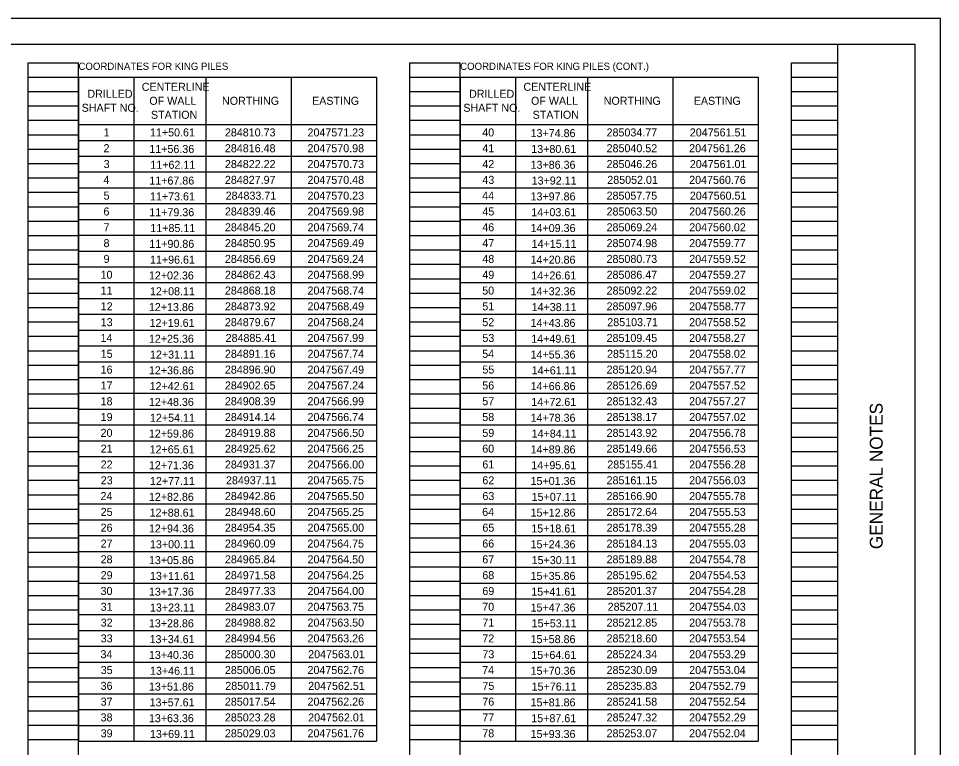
# Model space of a CAD drawing. Extents: x -15.5 to 34, y 0 to 22.
# Drawn here: x 16.07 to 34, y 7.82 to 22 of the extents above; entities that cross this region are included whole.
import ezdxf

# ---------------------------------------------------------------- set-up
doc = ezdxf.new("R2010")
doc.units = 0
for name, color, linetype in [('SH_Border', 7, 'Continuous'), ('SH_Cut_Line', 7, 'Continuous'), ('SH_Data', 7, 'Continuous'), ('SH_Text', 7, 'Continuous')]:
    doc.layers.add(name, color=color, linetype=linetype)

msp = doc.modelspace()

# ---------------------------------------------------------------- linework, layer by layer
at = {"layer": 'SH_Border'}
msp.add_line((32, 0.5), (32, 21.5), dxfattribs=at)
msp.add_lwpolyline([(1.5, 21.5), (33.5, 21.5), (33.5, 0.5), (1.5, 0.5)], close=True, dxfattribs=at)
at = {"layer": 'SH_Cut_Line'}
msp.add_lwpolyline([(0, 0), (34, 0), (34, 22), (0, 22)], close=True, dxfattribs=at)
at = {"layer": 'SH_Data'}
for p, q in [((16.26, 0.98), (16.26, 21.14)), ((16.26, 21.14), (17.24, 21.14)), ((17.24, 0.98), (17.24, 21.14)), ((23.68, 0.98), (23.68, 21.14)), ((23.68, 21.14), (24.66, 21.14)), ((24.66, 0.98), (24.66, 21.14)), ((31.1, 0.98), (31.1, 21.14)), ((31.1, 21.14), (32, 21.14)), ((32, 0.98), (32, 21.14)), ((16.26, 20.86), (17.24, 20.86)), ((23.68, 20.86), (24.66, 20.86)), ((31.1, 20.86), (32, 20.86)), ((16.26, 20.58), (17.24, 20.58)), ((23.68, 20.58), (24.66, 20.58)), ((31.1, 20.58), (32, 20.58)), ((16.26, 20.3), (17.24, 20.3)), ((23.68, 20.3), (24.66, 20.3)), ((31.1, 20.3), (32, 20.3)), ((16.26, 20.02), (17.24, 20.02)), ((23.68, 20.02), (24.66, 20.02)), ((31.1, 20.02), (32, 20.02)), ((16.26, 19.74), (17.24, 19.74)), ((23.68, 19.74), (24.66, 19.74)), ((31.1, 19.74), (32, 19.74)), ((16.26, 19.46), (17.24, 19.46)), ((23.68, 19.46), (24.66, 19.46)), ((31.1, 19.46), (32, 19.46)), ((16.26, 19.18), (17.24, 19.18)), ((23.68, 19.18), (24.66, 19.18)), ((31.1, 19.18), (32, 19.18)), ((16.26, 18.9), (17.24, 18.9)), ((23.68, 18.9), (24.66, 18.9)), ((31.1, 18.9), (32, 18.9)), ((16.26, 18.62), (17.24, 18.62)), ((23.68, 18.62), (24.66, 18.62)), ((31.1, 18.62), (32, 18.62)), ((16.26, 18.34), (17.24, 18.34)), ((23.68, 18.34), (24.66, 18.34)), ((31.1, 18.34), (32, 18.34)), ((16.26, 18.06), (17.24, 18.06)), ((23.68, 18.06), (24.66, 18.06)), ((31.1, 18.06), (32, 18.06)), ((16.26, 17.78), (17.24, 17.78)), ((23.68, 17.78), (24.66, 17.78)), ((31.1, 17.78), (32, 17.78)), ((16.26, 17.5), (17.24, 17.5)), ((23.68, 17.5), (24.66, 17.5)), ((31.1, 17.5), (32, 17.5)), ((16.26, 17.22), (17.24, 17.22)), ((23.68, 17.22), (24.66, 17.22)), ((31.1, 17.22), (32, 17.22)), ((16.26, 16.94), (17.24, 16.94)), ((23.68, 16.94), (24.66, 16.94)), ((31.1, 16.94), (32, 16.94)), ((16.26, 16.66), (17.24, 16.66)), ((23.68, 16.66), (24.66, 16.66)), ((31.1, 16.66), (32, 16.66)), ((16.26, 16.38), (17.24, 16.38)), ((23.68, 16.38), (24.66, 16.38)), ((31.1, 16.38), (32, 16.38)), ((16.26, 16.1), (17.24, 16.1)), ((23.68, 16.1), (24.66, 16.1)), ((31.1, 16.1), (32, 16.1)), ((16.26, 15.82), (17.24, 15.82)), ((23.68, 15.82), (24.66, 15.82)), ((31.1, 15.82), (32, 15.82)), ((16.26, 15.54), (17.24, 15.54)), ((23.68, 15.54), (24.66, 15.54)), ((31.1, 15.54), (32, 15.54)), ((16.26, 15.26), (17.24, 15.26)), ((23.68, 15.26), (24.66, 15.26)), ((31.1, 15.26), (32, 15.26)), ((16.26, 14.98), (17.24, 14.98)), ((23.68, 14.98), (24.66, 14.98)), ((31.1, 14.98), (32, 14.98)), ((16.26, 14.7), (17.24, 14.7)), ((23.68, 14.7), (24.66, 14.7)), ((31.1, 14.7), (32, 14.7)), ((16.26, 14.42), (17.24, 14.42)), ((23.68, 14.42), (24.66, 14.42)), ((31.1, 14.42), (32, 14.42)), ((16.26, 14.14), (17.24, 14.14)), ((23.68, 14.14), (24.66, 14.14)), ((31.1, 14.14), (32, 14.14)), ((16.26, 13.86), (17.24, 13.86)), ((23.68, 13.86), (24.66, 13.86)), ((31.1, 13.86), (32, 13.86)), ((16.26, 13.58), (17.24, 13.58)), ((23.68, 13.58), (24.66, 13.58)), ((31.1, 13.58), (32, 13.58)), ((16.26, 13.3), (17.24, 13.3)), ((23.68, 13.3), (24.66, 13.3)), ((31.1, 13.3), (32, 13.3)), ((16.26, 13.02), (17.24, 13.02)), ((23.68, 13.02), (24.66, 13.02)), ((31.1, 13.02), (32, 13.02)), ((16.26, 12.74), (17.24, 12.74)), ((23.68, 12.74), (24.66, 12.74)), ((31.1, 12.74), (32, 12.74)), ((16.26, 12.46), (17.24, 12.46)), ((23.68, 12.46), (24.66, 12.46)), ((31.1, 12.46), (32, 12.46)), ((16.26, 12.18), (17.24, 12.18)), ((23.68, 12.18), (24.66, 12.18)), ((31.1, 12.18), (32, 12.18)), ((16.26, 11.9), (17.24, 11.9)), ((23.68, 11.9), (24.66, 11.9)), ((31.1, 11.9), (32, 11.9)), ((16.26, 11.62), (17.24, 11.62)), ((23.68, 11.62), (24.66, 11.62)), ((31.1, 11.62), (32, 11.62)), ((16.26, 11.34), (17.24, 11.34)), ((23.68, 11.34), (24.66, 11.34)), ((31.1, 11.34), (32, 11.34)), ((16.26, 11.06), (17.24, 11.06)), ((23.68, 11.06), (24.66, 11.06)), ((31.1, 11.06), (32, 11.06)), ((16.26, 10.78), (17.24, 10.78)), ((23.68, 10.78), (24.66, 10.78)), ((31.1, 10.78), (32, 10.78)), ((16.26, 10.5), (17.24, 10.5)), ((23.68, 10.5), (24.66, 10.5)), ((31.1, 10.5), (32, 10.5)), ((16.26, 10.22), (17.24, 10.22)), ((23.68, 10.22), (24.66, 10.22)), ((31.1, 10.22), (32, 10.22)), ((16.26, 9.94), (17.24, 9.94)), ((23.68, 9.94), (24.66, 9.94)), ((31.1, 9.94), (32, 9.94)), ((16.26, 9.66), (17.24, 9.66)), ((23.68, 9.66), (24.66, 9.66)), ((31.1, 9.66), (32, 9.66)), ((16.26, 9.38), (17.24, 9.38)), ((23.68, 9.38), (24.66, 9.38)), ((31.1, 9.38), (32, 9.38)), ((16.26, 9.1), (17.24, 9.1)), ((23.68, 9.1), (24.66, 9.1)), ((31.1, 9.1), (32, 9.1)), ((16.26, 8.82), (17.24, 8.82)), ((23.68, 8.82), (24.66, 8.82)), ((31.1, 8.82), (32, 8.82)), ((16.26, 8.54), (17.24, 8.54)), ((23.68, 8.54), (24.66, 8.54)), ((31.1, 8.54), (32, 8.54)), ((16.26, 8.26), (17.24, 8.26)), ((23.68, 8.26), (24.66, 8.26)), ((31.1, 8.26), (32, 8.26)), ((16.26, 7.98), (17.24, 7.98)), ((23.68, 7.98), (24.66, 7.98)), ((31.1, 7.98), (32, 7.98))]:
    msp.add_line(p, q, dxfattribs=at)
at = {"layer": 'SH_Text'}
for p, q in [((17.24, 20.86), (23.035, 20.86)), ((17.24, 20.86), (17.24, 7.948)), ((18.316, 20.86), (18.316, 7.948)), ((19.715, 20.86), (19.715, 7.948)), ((21.375, 20.86), (21.375, 7.948)), ((23.035, 20.86), (23.035, 7.948)), ((24.66, 20.86), (30.455, 20.86)), ((24.66, 20.86), (24.66, 7.948)), ((25.736, 20.86), (25.736, 7.948)), ((27.135, 20.86), (27.135, 7.948)), ((28.795, 20.86), (28.795, 7.948)), ((30.455, 20.86), (30.455, 7.948)), ((17.24, 19.938), (23.035, 19.938)), ((24.66, 19.938), (30.455, 19.938)), ((17.24, 19.63), (23.035, 19.63)), ((24.66, 19.63), (30.455, 19.63)), ((17.24, 19.323), (23.035, 19.323)), ((24.66, 19.323), (30.455, 19.323)), ((17.24, 19.015), (23.035, 19.015)), ((24.66, 19.015), (30.455, 19.015)), ((17.24, 18.708), (23.035, 18.708)), ((24.66, 18.708), (30.455, 18.708)), ((17.24, 18.401), (23.035, 18.401)), ((24.66, 18.401), (30.455, 18.401)), ((17.24, 18.093), (23.035, 18.093)), ((24.66, 18.093), (30.455, 18.093)), ((17.24, 17.786), (23.035, 17.786)), ((24.66, 17.786), (30.455, 17.786)), ((17.24, 17.478), (23.035, 17.478)), ((24.66, 17.478), (30.455, 17.478)), ((17.24, 17.171), (23.035, 17.171)), ((24.66, 17.171), (30.455, 17.171)), ((17.24, 16.864), (23.035, 16.864)), ((24.66, 16.864), (30.455, 16.864)), ((17.24, 16.556), (23.035, 16.556)), ((24.66, 16.556), (30.455, 16.556)), ((17.24, 16.249), (23.035, 16.249)), ((24.66, 16.249), (30.455, 16.249)), ((17.24, 15.941), (23.035, 15.941)), ((24.66, 15.941), (30.455, 15.941)), ((17.24, 15.634), (23.035, 15.634)), ((24.66, 15.634), (30.455, 15.634)), ((17.24, 15.326), (23.035, 15.326)), ((24.66, 15.326), (30.455, 15.326)), ((17.24, 15.019), (23.035, 15.019)), ((24.66, 15.019), (30.455, 15.019)), ((17.24, 14.712), (23.035, 14.712)), ((24.66, 14.712), (30.455, 14.712)), ((17.24, 14.404), (23.035, 14.404)), ((24.66, 14.404), (30.455, 14.404)), ((17.24, 14.097), (23.035, 14.097)), ((24.66, 14.097), (30.455, 14.097)), ((17.24, 13.789), (23.035, 13.789)), ((24.66, 13.789), (30.455, 13.789)), ((17.24, 13.482), (23.035, 13.482)), ((24.66, 13.482), (30.455, 13.482)), ((17.24, 13.174), (23.035, 13.174)), ((24.66, 13.174), (30.455, 13.174)), ((17.24, 12.867), (23.035, 12.867)), ((24.66, 12.867), (30.455, 12.867)), ((17.24, 12.56), (23.035, 12.56)), ((24.66, 12.56), (30.455, 12.56)), ((17.24, 12.252), (23.035, 12.252)), ((24.66, 12.252), (30.455, 12.252)), ((17.24, 11.945), (23.035, 11.945)), ((24.66, 11.945), (30.455, 11.945)), ((17.24, 11.637), (23.035, 11.637)), ((24.66, 11.637), (30.455, 11.637)), ((17.24, 11.33), (23.035, 11.33)), ((24.66, 11.33), (30.455, 11.33)), ((17.24, 11.022), (23.035, 11.022)), ((24.66, 11.022), (30.455, 11.022)), ((17.24, 10.715), (23.035, 10.715)), ((24.66, 10.715), (30.455, 10.715)), ((17.24, 10.408), (23.035, 10.408)), ((24.66, 10.408), (30.455, 10.408)), ((17.24, 10.1), (23.035, 10.1)), ((24.66, 10.1), (30.455, 10.1)), ((17.24, 9.793), (23.035, 9.793)), ((24.66, 9.793), (30.455, 9.793)), ((17.24, 9.485), (23.035, 9.485)), ((24.66, 9.485), (30.455, 9.485)), ((17.24, 9.178), (23.035, 9.178)), ((24.66, 9.178), (30.455, 9.178)), ((17.24, 8.871), (23.035, 8.871)), ((24.66, 8.871), (30.455, 8.871)), ((17.24, 8.563), (23.035, 8.563)), ((24.66, 8.563), (30.455, 8.563)), ((17.24, 8.256), (23.035, 8.256)), ((24.66, 8.256), (30.455, 8.256)), ((17.24, 7.948), (23.035, 7.948)), ((24.66, 7.948), (30.455, 7.948))]:
    msp.add_line(p, q, dxfattribs=at)

# ---------------------------------------------------------------- texts
at = {"layer": 'SH_Data'}
msp.add_text('GENERAL NOTES', height=0.25, rotation=90, dxfattribs=at).set_placement((32.875, 11.682))
at = {"layer": 'SH_Text'}
for s, height, p in [('COORDINATES FOR KING PILES', 0.14, (17.24, 21)), ('COORDINATES FOR KING PILES (CONT.)', 0.14, (24.66, 21)), ('CENTERLINE ', 0.15556, (18.471, 20.593)), ('CENTERLINE ', 0.15556, (25.891, 20.593)), ('DRILLED ', 0.1556, (17.413, 20.457)), ('OF WALL ', 0.1556, (18.618, 20.321)), ('NORTHING', 0.1556, (20.031, 20.321)), ('EASTING', 0.1556, (21.782, 20.321)), ('DRILLED ', 0.1556, (24.833, 20.457)), ('OF WALL ', 0.1556, (26.038, 20.321)), ('NORTHING', 0.1556, (27.451, 20.321)), ('EASTING', 0.1556, (29.202, 20.321)), ('SHAFT NO.', 0.1556, (17.302, 20.185)), ('SHAFT NO.', 0.1556, (24.722, 20.185)), ('STATION', 0.1556, (18.649, 20.049)), ('STATION', 0.1556, (26.069, 20.049)), ('1', 0.156, (17.728, 19.706)), ('11+50.61', 0.1556, (18.63, 19.706)), ('284810.73', 0.1556, (20.087, 19.706)), ('2047571.23', 0.1556, (21.693, 19.706)), ('40', 0.1556, (25.09, 19.706)), ('13+74.86', 0.1556, (26.029, 19.692)), ('285034.77', 0.1556, (27.507, 19.706)), ('2047561.51', 0.1556, (29.126, 19.706)), ('2', 0.156, (17.728, 19.399)), ('11+56.36', 0.1556, (18.617, 19.384)), ('284816.48', 0.1556, (20.087, 19.399)), ('2047570.98', 0.1556, (21.693, 19.399)), ('41', 0.1556, (25.092, 19.399)), ('13+80.61', 0.1556, (26.043, 19.384)), ('285040.52', 0.1556, (27.508, 19.399)), ('2047561.26', 0.1556, (29.113, 19.399)), ('3', 0.156, (17.729, 19.091)), ('11+62.11', 0.1556, (18.637, 19.077)), ('284822.22', 0.1556, (20.088, 19.091)), ('2047570.73', 0.1556, (21.693, 19.091)), ('42', 0.1556, (25.092, 19.091)), ('13+86.36', 0.1556, (26.029, 19.077)), ('285046.26', 0.1556, (27.507, 19.091)), ('2047561.01', 0.1556, (29.126, 19.091)), ('4', 0.156, (17.725, 18.784)), ('11+67.86', 0.1556, (18.617, 18.77)), ('284827.97', 0.1556, (20.087, 18.784)), ('2047570.48', 0.1556, (21.693, 18.784)), ('43', 0.1556, (25.093, 18.784)), ('13+92.11', 0.1556, (26.05, 18.77)), ('285052.01', 0.1556, (27.521, 18.784)), ('2047560.76', 0.1556, (29.113, 18.784)), ('5', 0.156, (17.729, 18.477)), ('11+73.61', 0.1556, (18.63, 18.462)), ('284833.71', 0.1556, (20.101, 18.477)), ('2047570.23', 0.1556, (21.693, 18.477)), ('44', 0.1556, (25.089, 18.477)), ('13+97.86', 0.1556, (26.029, 18.462)), ('285057.75', 0.1556, (27.507, 18.477)), ('2047560.51', 0.1556, (29.126, 18.477)), ('6', 0.156, (17.726, 18.169)), ('11+79.36', 0.1556, (18.617, 18.155)), ('284839.46', 0.1556, (20.087, 18.169)), ('2047569.98', 0.1556, (21.693, 18.169)), ('45', 0.1556, (25.093, 18.169)), ('14+03.61', 0.1556, (26.043, 18.155)), ('285063.50', 0.1556, (27.507, 18.169)), ('2047560.26', 0.1556, (29.113, 18.169)), ('7', 0.156, (17.727, 17.862)), ('11+85.11', 0.1556, (18.637, 17.847)), ('284845.20', 0.1556, (20.087, 17.862)), ('2047569.74', 0.1556, (21.693, 17.862)), ('46', 0.1556, (25.091, 17.862)), ('14+09.36', 0.1556, (26.029, 17.847)), ('285069.24', 0.1556, (27.507, 17.862)), ('2047560.02', 0.1556, (29.114, 17.862)), ('8', 0.156, (17.727, 17.554)), ('11+90.86', 0.1556, (18.617, 17.54)), ('284850.95', 0.1556, (20.087, 17.554)), ('2047569.49', 0.1556, (21.693, 17.554)), ('47', 0.1556, (25.091, 17.554)), ('14+15.11', 0.1556, (26.05, 17.54)), ('285074.98', 0.1556, (27.507, 17.554)), ('2047559.77', 0.1556, (29.113, 17.554)), ('9', 0.156, (17.728, 17.247)), ('11+96.61', 0.1556, (18.63, 17.232)), ('284856.69', 0.1556, (20.087, 17.247)), ('2047569.24', 0.1556, (21.693, 17.247)), ('48', 0.1556, (25.091, 17.247)), ('14+20.86', 0.1556, (26.029, 17.232)), ('285080.73', 0.1556, (27.507, 17.247)), ('2047559.52', 0.1556, (29.114, 17.247)), ('10', 0.1556, (17.67, 16.939)), ('12+02.36', 0.1556, (18.609, 16.925)), ('284862.43', 0.1556, (20.087, 16.939)), ('2047568.99', 0.1556, (21.693, 16.939)), ('49', 0.1556, (25.092, 16.939)), ('14+26.61', 0.1556, (26.043, 16.925)), ('285086.47', 0.1556, (27.507, 16.939)), ('2047559.27', 0.1556, (29.113, 16.939)), ('11', 0.1556, (17.672, 16.632)), ('12+08.11', 0.1556, (18.63, 16.618)), ('284868.18', 0.1556, (20.087, 16.632)), ('2047568.74', 0.1556, (21.693, 16.632)), ('50', 0.1556, (25.09, 16.632)), ('14+32.36', 0.1556, (26.029, 16.618)), ('285092.22', 0.1556, (27.508, 16.632)), ('2047559.02', 0.1556, (29.114, 16.632)), ('12', 0.1556, (17.672, 16.325)), ('12+13.86', 0.1556, (18.609, 16.31)), ('284873.92', 0.1556, (20.088, 16.325)), ('2047568.49', 0.1556, (21.693, 16.325)), ('51', 0.1556, (25.092, 16.325)), ('14+38.11', 0.1556, (26.05, 16.31)), ('285097.96', 0.1556, (27.507, 16.325)), ('2047558.77', 0.1556, (29.113, 16.325)), ('13', 0.1556, (17.673, 16.017)), ('12+19.61', 0.1556, (18.623, 16.003)), ('284879.67', 0.1556, (20.087, 16.017)), ('2047568.24', 0.1556, (21.693, 16.017)), ('52', 0.1556, (25.092, 16.017)), ('14+43.86', 0.1556, (26.029, 16.003)), ('285103.71', 0.1556, (27.521, 16.017)), ('2047558.52', 0.1556, (29.114, 16.017)), ('14', 0.1556, (17.669, 15.71)), ('12+25.36', 0.1556, (18.609, 15.695)), ('284885.41', 0.1556, (20.101, 15.71)), ('2047567.99', 0.1556, (21.693, 15.71)), ('53', 0.1556, (25.093, 15.71)), ('14+49.61', 0.1556, (26.043, 15.695)), ('285109.45', 0.1556, (27.507, 15.71)), ('2047558.27', 0.1556, (29.113, 15.71)), ('15', 0.1556, (17.673, 15.402)), ('12+31.11', 0.1556, (18.63, 15.388)), ('284891.16', 0.1556, (20.087, 15.402)), ('2047567.74', 0.1556, (21.693, 15.402)), ('54', 0.1556, (25.089, 15.402)), ('14+55.36', 0.1556, (26.029, 15.388)), ('285115.20', 0.1556, (27.515, 15.402)), ('2047558.02', 0.1556, (29.114, 15.402)), ('16', 0.1556, (17.671, 15.095)), ('12+36.86', 0.1556, (18.609, 15.08)), ('284896.90', 0.1556, (20.087, 15.095)), ('2047567.49', 0.1556, (21.693, 15.095)), ('55', 0.1556, (25.093, 15.095)), ('14+61.11', 0.1556, (26.05, 15.08)), ('285120.94', 0.1556, (27.507, 15.095)), ('2047557.77', 0.1556, (29.113, 15.095)), ('17', 0.1556, (17.671, 14.787)), ('12+42.61', 0.1556, (18.623, 14.773)), ('284902.65', 0.1556, (20.087, 14.787)), ('2047567.24', 0.1556, (21.693, 14.787)), ('56', 0.1556, (25.091, 14.787)), ('14+66.86', 0.1556, (26.029, 14.773)), ('285126.69', 0.1556, (27.507, 14.787)), ('2047557.52', 0.1556, (29.114, 14.787)), ('18', 0.1556, (17.671, 14.48)), ('12+48.36', 0.1556, (18.609, 14.466)), ('284908.39', 0.1556, (20.087, 14.48)), ('2047566.99', 0.1556, (21.693, 14.48)), ('57', 0.1556, (25.091, 14.48)), ('14+72.61', 0.1556, (26.043, 14.466)), ('285132.43', 0.1556, (27.507, 14.48)), ('2047557.27', 0.1556, (29.113, 14.48)), ('19', 0.1556, (17.672, 14.173)), ('12+54.11', 0.1556, (18.63, 14.158)), ('284914.14', 0.1556, (20.087, 14.173)), ('2047566.74', 0.1556, (21.693, 14.173)), ('58', 0.1556, (25.091, 14.173)), ('14+78.36', 0.1556, (26.029, 14.158)), ('285138.17', 0.1556, (27.507, 14.173)), ('2047557.02', 0.1556, (29.114, 14.173)), ('20', 0.1556, (17.67, 13.865)), ('12+59.86', 0.1556, (18.609, 13.851)), ('284919.88', 0.1556, (20.087, 13.865)), ('2047566.50', 0.1556, (21.693, 13.865)), ('59', 0.1556, (25.092, 13.865)), ('14+84.11', 0.1556, (26.05, 13.851)), ('285143.92', 0.1556, (27.508, 13.865)), ('2047556.78', 0.1556, (29.113, 13.865)), ('21', 0.1556, (17.672, 13.558)), ('12+65.61', 0.1556, (18.623, 13.543)), ('284925.62', 0.1556, (20.088, 13.558)), ('2047566.25', 0.1556, (21.692, 13.558)), ('60', 0.1556, (25.09, 13.558)), ('14+89.86', 0.1556, (26.029, 13.543)), ('285149.66', 0.1556, (27.507, 13.558)), ('2047556.53', 0.1556, (29.113, 13.558)), ('22', 0.1556, (17.672, 13.25)), ('12+71.36', 0.1556, (18.609, 13.236)), ('284931.37', 0.1556, (20.087, 13.25)), ('2047566.00', 0.1556, (21.693, 13.25)), ('61', 0.1556, (25.092, 13.25)), ('14+95.61', 0.1556, (26.043, 13.236)), ('285155.41', 0.1556, (27.521, 13.25)), ('2047556.28', 0.1556, (29.113, 13.25)), ('23', 0.1556, (17.673, 12.943)), ('284937.11', 0.1556, (20.108, 12.943)), ('2047565.75', 0.1556, (21.692, 12.943)), ('62', 0.1556, (25.092, 12.943)), ('285161.15', 0.1556, (27.507, 12.943)), ('2047556.03', 0.1556, (29.113, 12.943)), ('12+77.11', 0.1556, (18.63, 12.929)), ('15+01.36', 0.1556, (26.029, 12.929)), ('24', 0.1556, (17.669, 12.636)), ('12+82.86', 0.1556, (18.609, 12.621)), ('284942.86', 0.1556, (20.087, 12.636)), ('2047565.50', 0.1556, (21.693, 12.636)), ('63', 0.1556, (25.093, 12.636)), ('15+07.11', 0.1556, (26.05, 12.621)), ('285166.90', 0.1556, (27.507, 12.636)), ('2047555.78', 0.1556, (29.113, 12.636)), ('25', 0.1556, (17.673, 12.328)), ('12+88.61', 0.1556, (18.623, 12.314)), ('284948.60', 0.1556, (20.087, 12.328)), ('2047565.25', 0.1556, (21.692, 12.328)), ('64', 0.1556, (25.089, 12.328)), ('15+12.86', 0.1556, (26.029, 12.314)), ('285172.64', 0.1556, (27.507, 12.328)), ('2047555.53', 0.1556, (29.113, 12.328)), ('26', 0.1556, (17.671, 12.021)), ('12+94.36', 0.1556, (18.609, 12.006)), ('284954.35', 0.1556, (20.087, 12.021)), ('2047565.00', 0.1556, (21.693, 12.021)), ('65', 0.1556, (25.093, 12.021)), ('15+18.61', 0.1556, (26.043, 12.006)), ('285178.39', 0.1556, (27.507, 12.021)), ('2047555.28', 0.1556, (29.113, 12.021)), ('27', 0.1556, (17.671, 11.713)), ('13+00.11', 0.1556, (18.63, 11.699)), ('284960.09', 0.1556, (20.087, 11.713)), ('2047564.75', 0.1556, (21.692, 11.713)), ('66', 0.1556, (25.091, 11.713)), ('15+24.36', 0.1556, (26.029, 11.699)), ('285184.13', 0.1556, (27.507, 11.713)), ('2047555.03', 0.1556, (29.113, 11.713)), ('28', 0.1556, (17.671, 11.406)), ('13+05.86', 0.1556, (18.609, 11.391)), ('284965.84', 0.1556, (20.087, 11.406)), ('2047564.50', 0.1556, (21.693, 11.406)), ('67', 0.1556, (25.091, 11.406)), ('15+30.11', 0.1556, (26.05, 11.391)), ('285189.88', 0.1556, (27.507, 11.406)), ('2047554.78', 0.1556, (29.113, 11.406)), ('29', 0.1556, (17.672, 11.098)), ('13+11.61', 0.1556, (18.63, 11.084)), ('284971.58', 0.1556, (20.087, 11.098)), ('2047564.25', 0.1556, (21.692, 11.098)), ('68', 0.1556, (25.091, 11.098)), ('15+35.86', 0.1556, (26.029, 11.084)), ('285195.62', 0.1556, (27.508, 11.098)), ('2047554.53', 0.1556, (29.113, 11.098)), ('30', 0.1556, (17.67, 10.791)), ('284977.33', 0.1556, (20.087, 10.791)), ('2047564.00', 0.1556, (21.693, 10.791)), ('69', 0.1556, (25.092, 10.791)), ('285201.37', 0.1556, (27.507, 10.791)), ('2047554.28', 0.1556, (29.113, 10.791)), ('13+17.36', 0.1556, (18.609, 10.777)), ('15+41.61', 0.1556, (26.043, 10.777)), ('31', 0.1556, (17.672, 10.484)), ('13+23.11', 0.1556, (18.63, 10.469)), ('284983.07', 0.1556, (20.087, 10.484)), ('2047563.75', 0.1556, (21.692, 10.484)), ('70', 0.1556, (25.09, 10.484)), ('15+47.36', 0.1556, (26.029, 10.469)), ('285207.11', 0.1556, (27.528, 10.484)), ('2047554.03', 0.1556, (29.113, 10.484)), ('32', 0.1556, (17.672, 10.176)), ('13+28.86', 0.1556, (18.609, 10.162)), ('284988.82', 0.1556, (20.088, 10.176)), ('2047563.50', 0.1556, (21.693, 10.176)), ('71', 0.1556, (25.092, 10.176)), ('15+53.11', 0.1556, (26.05, 10.162)), ('285212.85', 0.1556, (27.507, 10.176)), ('2047553.78', 0.1556, (29.113, 10.176)), ('33', 0.1556, (17.673, 9.869)), ('13+34.61', 0.1556, (18.623, 9.854)), ('284994.56', 0.1556, (20.087, 9.869)), ('2047563.26', 0.1556, (21.693, 9.869)), ('72', 0.1556, (25.092, 9.869)), ('15+58.86', 0.1556, (26.029, 9.854)), ('285218.60', 0.1556, (27.507, 9.869)), ('2047553.54', 0.1556, (29.113, 9.869)), ('34', 0.1556, (17.669, 9.561)), ('13+40.36', 0.1556, (18.609, 9.547)), ('285000.30', 0.1556, (20.087, 9.561)), ('2047563.01', 0.1556, (21.706, 9.561)), ('73', 0.1556, (25.093, 9.561)), ('15+64.61', 0.1556, (26.043, 9.547)), ('285224.34', 0.1556, (27.507, 9.561)), ('2047553.29', 0.1556, (29.113, 9.561)), ('35', 0.1556, (17.673, 9.254)), ('13+46.11', 0.1556, (18.63, 9.239)), ('285006.05', 0.1556, (20.087, 9.254)), ('2047562.76', 0.1556, (21.693, 9.254)), ('74', 0.1556, (25.089, 9.254)), ('15+70.36', 0.1556, (26.029, 9.239)), ('285230.09', 0.1556, (27.507, 9.254)), ('2047553.04', 0.1556, (29.113, 9.254)), ('36', 0.1556, (17.671, 8.946)), ('13+51.86', 0.1556, (18.609, 8.932)), ('285011.79', 0.1556, (20.094, 8.946)), ('2047562.51', 0.1556, (21.706, 8.946)), ('75', 0.1556, (25.093, 8.946)), ('15+76.11', 0.1556, (26.05, 8.932)), ('285235.83', 0.1556, (27.507, 8.946)), ('2047552.79', 0.1556, (29.113, 8.946)), ('37', 0.1556, (17.671, 8.639)), ('285017.54', 0.1556, (20.087, 8.639)), ('2047562.26', 0.1556, (21.693, 8.639)), ('76', 0.1556, (25.091, 8.639)), ('285241.58', 0.1556, (27.507, 8.639)), ('2047552.54', 0.1556, (29.113, 8.639)), ('13+57.61', 0.1556, (18.623, 8.625)), ('15+81.86', 0.1556, (26.029, 8.625)), ('38', 0.1556, (17.671, 8.332)), ('13+63.36', 0.1556, (18.609, 8.317)), ('285023.28', 0.1556, (20.087, 8.332)), ('2047562.01', 0.1556, (21.706, 8.332)), ('77', 0.1556, (25.091, 8.332)), ('15+87.61', 0.1556, (26.043, 8.317)), ('285247.32', 0.1556, (27.508, 8.332)), ('2047552.29', 0.1556, (29.113, 8.332)), ('39', 0.1556, (17.672, 8.024)), ('13+69.11', 0.1556, (18.63, 8.01)), ('285029.03', 0.1556, (20.087, 8.024)), ('2047561.76', 0.1556, (21.693, 8.024)), ('78', 0.1556, (25.091, 8.024)), ('15+93.36', 0.1556, (26.029, 8.01)), ('285253.07', 0.1556, (27.507, 8.024)), ('2047552.04', 0.1556, (29.113, 8.024))]:
    msp.add_text(s, height=height, dxfattribs=at).set_placement(p)

doc.saveas('drawing.dxf')
